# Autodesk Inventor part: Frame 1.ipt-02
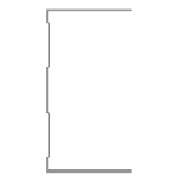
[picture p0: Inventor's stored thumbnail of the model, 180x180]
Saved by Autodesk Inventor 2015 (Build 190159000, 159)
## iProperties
Created: 2015-04
Part Number: Frame 1.ipt-02
Material: Aluminum 6061
Description: Kévin Novo
Document SubType Name: Modeling
Standard: Kevin
Designer: suporte
Standards Organization: Kevin
Language: en-US
Size Designation: (Unnamed 2)
Categories: <MemberInstance><Categories><Category DisplayName="Structural Shapes" InternalName="089c4875-fa83-4c05-b084-43b9cc11f5ed" Mnemonic="GRDR"><CategoryParameter Dis
Density: 2.7 g/cm^3
Appearance: Aluminum - Flat
IsCustomPart: 1
G_W: 50,000 mm
G_H: 75,000 mm
G_L: 2100,000 mm
_CCFamilyMember: 2
_CCFamilyDisplayName: Kévin - Kévin Novo
_FrameMemberDoc: Frame Member File
_Version: 15.0.0
_GetPNFromCC: 1
Author: suporte
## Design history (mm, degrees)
node "Start Plane"
node "End Plane"
sketch "Sketch"
  geometry: L1 (24.7, 37.5)-(24.7, 36.9); L2 (24.7, 36.9)-(-24.7, 36.9); L3 (-24.7, -36.9)-(24.7, -36.9); L4 (24.7, -36.9)-(24.7, -37.5); L5 (24.7, -37.5)-(-25.3, -37.5); L6 (-25.3, 37.5)-(24.7, 37.5); L7 (-24.7, 36.9)-(-24.7, 31.9); L8 (-24.7, 31.9)-(-23.3, 30.5); L9 (-23.3, 30.5)-(-23.3, 10.934); L10 (-23.3, 10.934)-(-24.7, 9.534); L11 (-24.7, 9.534)-(-24.7, -9.534); L12 (-24.7, -9.534)-(-23.3, -10.934); L13 (-23.3, -10.934)-(-23.3, -30.5); L14 (-23.3, -30.5)-(-24.7, -31.9); L15 (-24.7, -31.9)-(-24.7, -36.9); L16 (-25.3, -37.5)-(-25.3, -31.651); L17 (-25.3, -31.651)-(-23.9, -30.251); L18 (-23.9, -30.251)-(-23.9, -11.183); L19 (-23.9, -11.183)-(-25.3, -9.783); L20 (-25.3, -9.783)-(-25.3, 9.783); L21 (-25.3, 9.783)-(-23.9, 11.183); L22 (-23.9, 11.183)-(-23.9, 30.251); L23 (-23.9, 30.251)-(-25.3, 31.651); L24 (-25.3, 31.651)-(-25.3, 37.5); L25 (-25.3, 0)-(30.37, 0); 3 further points
  constraints: 50 end point, 10 point on line, 9 parallel, 5 perpendicular, 4 equal length, 3 midpoint, 3 vertical, 2 vertical alignment, 1 collinear, 1 horizontal, 1 horizontal alignment
  dimensions: "d3" = 0.6 distance of L1.start L1.end (= d6); "d5" = 75 distance between parallel lines of L5 L6; "d6" = 0.6 distance between parallel lines of L24 L7 (= d8); "d7" = 0.6 distance between parallel lines of L8 L23 (= d8); "d8" = 0.6 distance between parallel lines of L22 L9 (= d12); "Espessura" = 0.6 distance between parallel lines of L17 L14; "d10" = 0.6 distance between parallel lines of L13 L18 (= Espessura); "d11" = 0.6 distance between parallel lines of L12 L19 (= Espessura); "d12" = 0.6 distance between parallel lines of L21 L10 (= d11); "d13" = 5 distance of L2.end L7.end; "d15" = 135 deg angle of L9 L8; "d16" = 2 distance between parallel lines of L24 L9; "d17" = 50 distance of L6.start L1.start
extrude "Body" join sketch "Sketch" stored distance "d24" = 0.13; taper "d25" = 0 deg
node "Driven Length"
  sketch "Sketch10"
    geometry: L1 (0, 0)-(10, 0) reference
    constraints: 2 end point, 1 horizontal
  workplane "Work Plane7"
  sketch "Sketch11"
    geometry: L1 (-2, 0)-(12, 0) reference; L2 (-2, 2100)-(12, 2100) reference
    dimensions: "d27" = 2100 distance between parallel lines of L1 L2 (derived)
body "Solid1"
other parameters: "G_OFFSET_START" = 0 [user parameter; used in 1 equation term], "G_OFFSET_END" = 0 [user parameter; used in 1 equation term], "d22" = 0 (computed from G_OFFSET_START), "G_L" = 2100 (= d27) [user parameter], "d34" = 90 deg
